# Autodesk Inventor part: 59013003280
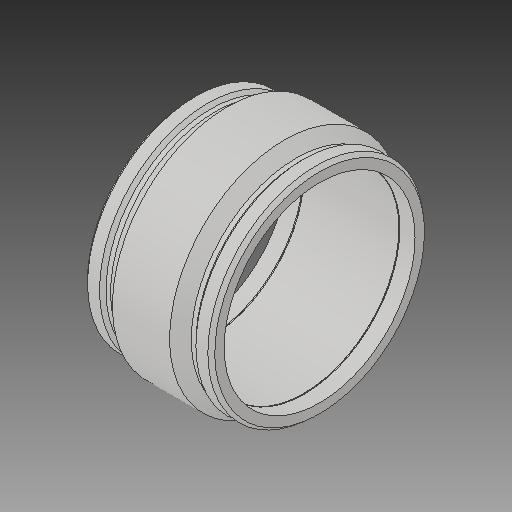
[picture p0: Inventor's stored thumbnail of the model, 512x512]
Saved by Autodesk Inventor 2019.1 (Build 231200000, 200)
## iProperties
Created: 2017-06
Part Number: 59013003280
Material: Generic
Description: PLASSON IPS COUPLER 28''
Document SubType Name: Modeling
Designer: KIM
Mass: 8622.19 g
Surface Area: 6772.47 cm^2
Volume: 8622.19 cm^3
Density: 1 g/cm^3
Appearance: Default
Author: KIM
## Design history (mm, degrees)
derived "5901B.ipt"
feature "Solid1::5901B.ipt"
tag "TaggingFeature1"
body "Solid1"
other parameters: "d0" = 471.932, "d1" = 708, "d2" = 852.932, "d3" = 235.966, "d4" = 117.983, "d5" = 767.6388, "d6" = 566.4, "d7" = 708, "d8" = 168 deg, "d10" = 94.3864, "d11" = 31.46213, "d13" = 471.932, "d14" = 17.6296, "d18" = 708, "d19" = 3.52592, "d20" = 168 deg, "d22" = 801.75608, "d23" = 852.932, "d24" = 777.7034, "d25" = 135 deg, "d26" = 212.3694, "d27" = 135 deg, "d29" = 399.542, "d30" = 15, "d31" = 165.1762, "d34" = 5 deg, "d35" = 15, "d39" = 5 deg, "d41" = 4, "d42" = 14, "d43" = 0, "d45" = 4, "d46" = 14, "d47" = 0, "d48" = 3, "d49" = 0, "d50" = 3, "d51" = 0, "d52" = 68.43014, "d53" = 17.10753, "d55" = 235.966, "d_" = 708, "L_" = 471.932, "L_1" = 235.966, "D_" = 852.932, "A_" = 399.542, "d_2" = 12, "B_" = 399.542
